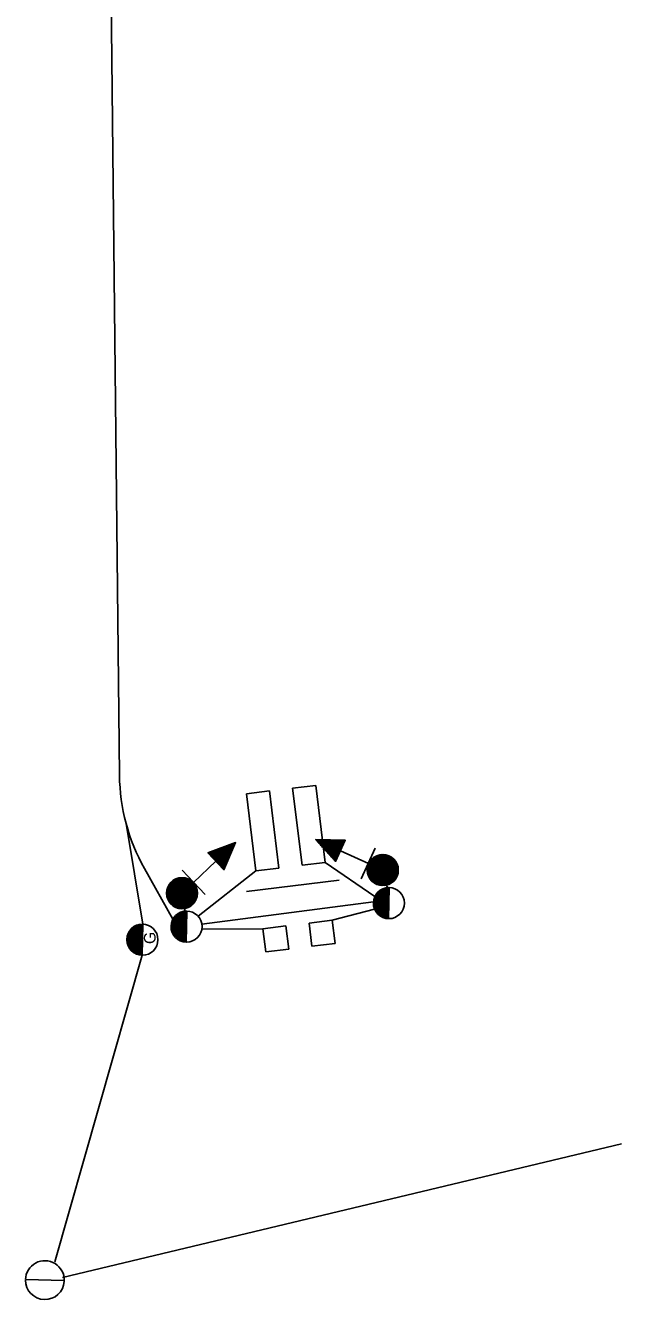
# Model space of a CAD drawing. Extents: x 584850 to 602551, y 145475 to 158627.
# Drawn here: x 585421.3 to 585574.8, y 151816.7 to 152144.7 of the extents above; entities that cross this region are included whole.
import ezdxf

# ---------------------------------------------------------------- set-up
doc = ezdxf.new("R2010")
doc.units = 0
doc.layers.add('Default', color=7, linetype='Continuous')
doc.layers.add('P_LTG', color=7, linetype='Continuous')

msp = doc.modelspace()

# ---------------------------------------------------------------- linework, layer by layer
at = {"layer": 'Default'}
for p, q in [((585442.26, 152251.68), (585445.51, 151951.65)), ((585490.11, 151948.32), (585496.07, 151949.05)), ((585490.11, 151948.32), (585492.53, 151928.47)), ((585496.07, 151949.05), (585498.49, 151929.2)), ((585478.2, 151946.87), (585484.15, 151947.6)), ((585478.2, 151946.87), (585480.62, 151927.02)), ((585484.15, 151947.6), (585486.58, 151927.74)), ((585451.49, 151913.31), (585447.21, 151939.25)), ((585468.86, 151931.91), (585468.83, 151931.11)), ((585469.11, 151932), (585469.07, 151930.85)), ((585469.11, 151932), (585474.36, 151931.84)), ((585469.36, 151932.09), (585469.32, 151930.59)), ((585469.61, 151932.18), (585469.56, 151930.33)), ((585469.74, 151932.23), (585474.46, 151932.09)), ((585469.87, 151932.28), (585469.8, 151930.08)), ((585470.12, 151932.37), (585470.05, 151929.82)), ((585470.37, 151932.46), (585470.29, 151929.56)), ((585470.37, 151932.46), (585474.57, 151932.34)), ((585470.63, 151932.55), (585470.53, 151929.31)), ((585470.88, 151932.65), (585470.77, 151929.05)), ((585471, 151932.69), (585474.68, 151932.59)), ((585471.13, 151932.74), (585471.02, 151928.79)), ((585471.38, 151932.83), (585471.26, 151928.53)), ((585471.64, 151932.92), (585471.5, 151928.28)), ((585471.64, 151932.92), (585474.79, 151932.83)), ((585471.89, 151933.02), (585471.74, 151928.02)), ((585472.14, 151933.11), (585471.99, 151927.76)), ((585472.39, 151933.2), (585472.23, 151927.51)), ((585472.27, 151933.16), (585474.89, 151933.08)), ((585472.65, 151933.29), (585472.48, 151927.52)), ((585472.9, 151933.39), (585472.75, 151928.14)), ((585472.9, 151933.39), (585475, 151933.33)), ((585473.15, 151933.48), (585473.02, 151928.76)), ((585473.41, 151933.57), (585473.28, 151929.37)), ((585473.53, 151933.62), (585475.11, 151933.57)), ((585473.66, 151933.67), (585473.55, 151929.99)), ((585473.91, 151933.76), (585473.82, 151930.61)), ((585474.16, 151933.85), (585474.09, 151931.23)), ((585474.16, 151933.85), (585475.21, 151933.82)), ((585474.42, 151933.94), (585474.36, 151931.84)), ((585474.67, 151934.04), (585474.62, 151932.46)), ((585474.8, 151934.08), (585475.32, 151934.07)), ((585474.92, 151934.13), (585474.89, 151933.08)), ((585475.18, 151934.22), (585475.16, 151933.7)), ((585475.43, 151934.31), (585475.43, 151934.31)), ((585496.02, 151935.07), (585496.02, 151935.07)), ((585496.2, 151934.87), (585496.69, 151935.06)), ((585496.47, 151934.58), (585496.29, 151935.07)), ((585496.38, 151934.68), (585497.37, 151935.05)), ((585496.93, 151934.08), (585496.56, 151935.06)), ((585496.57, 151934.48), (585498.04, 151935.03)), ((585496.75, 151934.28), (585498.71, 151935.02)), ((585497.38, 151933.58), (585496.83, 151935.06)), ((585496.93, 151934.08), (585499.39, 151935)), ((585497.84, 151933.09), (585497.1, 151935.05)), ((585497.11, 151933.88), (585500.06, 151934.99)), ((585497.29, 151933.68), (585500.73, 151934.98)), ((585498.29, 151932.59), (585497.37, 151935.05)), ((585497.47, 151933.48), (585501.4, 151934.96)), ((585498.74, 151932.09), (585497.64, 151935.04)), ((585497.66, 151933.28), (585502.08, 151934.95)), ((585497.84, 151933.09), (585502.75, 151934.93)), ((585499.2, 151931.59), (585497.91, 151935.03)), ((585498.02, 151932.89), (585503.42, 151934.92)), ((585499.65, 151931.1), (585498.17, 151935.03)), ((585498.2, 151932.69), (585503.53, 151934.69)), ((585498.38, 151932.49), (585503.39, 151934.37)), ((585500.11, 151930.6), (585498.44, 151935.02)), ((585498.56, 151932.29), (585503.24, 151934.05)), ((585500.56, 151930.1), (585498.71, 151935.02)), ((585498.74, 151932.09), (585503.1, 151933.73)), ((585498.93, 151931.89), (585502.95, 151933.41)), ((585501.01, 151929.61), (585498.98, 151935.01)), ((585499.11, 151931.69), (585502.8, 151933.08)), ((585501.26, 151929.67), (585499.25, 151935.01)), ((585499.29, 151931.5), (585502.66, 151932.76)), ((585499.47, 151931.3), (585502.51, 151932.44)), ((585501.4, 151929.99), (585499.52, 151935)), ((585499.65, 151931.1), (585502.37, 151932.12)), ((585501.55, 151930.32), (585499.79, 151935)), ((585501.7, 151930.64), (585500.06, 151934.99)), ((585501.84, 151930.96), (585500.33, 151934.98)), ((585501.99, 151931.28), (585500.6, 151934.98)), ((585502.13, 151931.6), (585500.87, 151934.97)), ((585502.28, 151931.93), (585501.14, 151934.97)), ((585502.43, 151932.25), (585501.4, 151934.96)), ((585502.57, 151932.57), (585501.67, 151934.96)), ((585502.72, 151932.89), (585501.94, 151934.95)), ((585502.86, 151933.21), (585502.21, 151934.94)), ((585509.65, 151928.89), (585502.4, 151932.18)), ((585503.01, 151933.54), (585502.48, 151934.94)), ((585503.16, 151933.86), (585502.75, 151934.93)), ((585503.3, 151934.18), (585503.02, 151934.93)), ((585503.45, 151934.5), (585503.29, 151934.92)), ((585503.59, 151934.82), (585503.56, 151934.92)), ((585509.56, 151928.93), (585511.33, 151932.84)), ((585464.54, 151924.05), (585470.34, 151929.51)), ((585468.35, 151931.72), (585468.35, 151931.62)), ((585468.44, 151931.52), (585474.14, 151931.35)), ((585468.48, 151931.77), (585474.25, 151931.6)), ((585468.6, 151931.81), (585468.59, 151931.36)), ((585468.69, 151931.26), (585474.03, 151931.1)), ((585468.93, 151931), (585473.93, 151930.86)), ((585469.17, 151930.75), (585473.82, 151930.61)), ((585469.41, 151930.49), (585473.71, 151930.36)), ((585469.66, 151930.23), (585473.61, 151930.12)), ((585469.9, 151929.97), (585473.5, 151929.87)), ((585470.14, 151929.72), (585473.39, 151929.62)), ((585470.39, 151929.46), (585473.28, 151929.37)), ((585470.63, 151929.2), (585473.18, 151929.13)), ((585470.87, 151928.94), (585473.07, 151928.88)), ((585471.11, 151928.69), (585472.96, 151928.63)), ((585492.53, 151928.47), (585498.49, 151929.2)), ((585498.49, 151929.2), (585511.28, 151920.42)), ((585499.83, 151930.9), (585502.22, 151931.8)), ((585500.02, 151930.7), (585502.07, 151931.47)), ((585500.2, 151930.5), (585501.93, 151931.15)), ((585500.38, 151930.3), (585501.78, 151930.83)), ((585500.56, 151930.1), (585501.64, 151930.51)), ((585500.74, 151929.9), (585501.49, 151930.19)), ((585500.92, 151929.71), (585501.34, 151929.86)), ((585501.11, 151929.51), (585501.2, 151929.54)), ((585509.56, 151928.93), (585507.79, 151925.02)), ((585509.34, 151927.27), (585516.3, 151929.88)), ((585509.34, 151927.01), (585516.47, 151929.69)), ((585509.35, 151927.53), (585516.13, 151930.08)), ((585509.37, 151927.79), (585515.92, 151930.25)), ((585509.37, 151926.76), (585516.61, 151929.49)), ((585509.4, 151926.52), (585516.74, 151929.28)), ((585509.43, 151928.07), (585515.7, 151930.43)), ((585509.45, 151926.28), (585516.87, 151929.07)), ((585509.49, 151928.35), (585515.47, 151930.6)), ((585509.52, 151926.05), (585516.97, 151928.85)), ((585509.59, 151925.82), (585517.06, 151928.63)), ((585509.6, 151928.65), (585515.19, 151930.75)), ((585511.6, 151923.63), (585509.66, 151928.79)), ((585509.72, 151928.95), (585514.9, 151930.9)), ((585511.91, 151923.49), (585509.8, 151929.1)), ((585509.9, 151929.27), (585514.55, 151931.02)), ((585512.2, 151923.4), (585509.96, 151929.36)), ((585510.11, 151929.61), (585514.15, 151931.13)), ((585512.48, 151923.33), (585510.12, 151929.62)), ((585512.76, 151923.28), (585510.3, 151929.82)), ((585510.45, 151929.99), (585513.69, 151931.21)), ((585513.02, 151923.25), (585510.48, 151930.02)), ((585513.29, 151923.23), (585510.67, 151930.2)), ((585513.54, 151923.25), (585510.86, 151930.36)), ((585510.96, 151930.44), (585513.02, 151931.21)), ((585513.79, 151923.27), (585511.06, 151930.52)), ((585514.03, 151923.29), (585511.27, 151930.65)), ((585514.27, 151923.35), (585511.48, 151930.76)), ((585514.5, 151923.41), (585511.7, 151930.88)), ((585514.73, 151923.49), (585511.92, 151930.96)), ((585514.95, 151923.59), (585512.15, 151931.04)), ((585515.17, 151923.69), (585512.38, 151931.11)), ((585515.38, 151923.81), (585512.62, 151931.15)), ((585515.59, 151923.94), (585512.86, 151931.19)), ((585515.79, 151924.08), (585513.11, 151931.21)), ((585515.98, 151924.25), (585513.36, 151931.21)), ((585516.17, 151924.43), (585513.62, 151931.21)), ((585516.36, 151924.62), (585513.89, 151931.17)), ((585516.53, 151924.85), (585514.17, 151931.13)), ((585516.7, 151925.08), (585514.45, 151931.06)), ((585516.85, 151925.36), (585514.74, 151930.95)), ((585516.99, 151925.65), (585515.05, 151930.83)), ((585517.12, 151926), (585515.37, 151930.65)), ((585517.23, 151926.38), (585515.71, 151930.42)), ((585517.3, 151926.89), (585516.08, 151930.12)), ((585517.3, 151927.57), (585516.53, 151929.62)), ((585451.94, 151927.66), (585459.28, 151914.62)), ((585464.61, 151924.11), (585461.67, 151927.24)), ((585480.62, 151927.02), (585465.74, 151915.38)), ((585471.36, 151928.43), (585472.85, 151928.39)), ((585471.6, 151928.17), (585472.75, 151928.14)), ((585471.84, 151927.92), (585472.64, 151927.89)), ((585472.08, 151927.66), (585472.53, 151927.65)), ((585472.33, 151927.4), (585472.43, 151927.4)), ((585480.62, 151927.02), (585486.58, 151927.74)), ((585510.56, 151924.36), (585509.35, 151927.57)), ((585510.11, 151924.88), (585509.35, 151926.89)), ((585510.94, 151924.03), (585509.43, 151928.05)), ((585511.28, 151923.8), (585509.53, 151928.46)), ((585509.68, 151925.6), (585517.15, 151928.41)), ((585509.79, 151925.39), (585517.2, 151928.17)), ((585509.9, 151925.17), (585517.25, 151927.93)), ((585510.04, 151924.97), (585517.3, 151927.69)), ((585510.19, 151924.77), (585517.31, 151927.44)), ((585510.34, 151924.57), (585517.32, 151927.19)), ((585510.53, 151924.38), (585517.31, 151926.93)), ((585510.72, 151924.2), (585517.27, 151926.66)), ((585510.95, 151924.02), (585517.24, 151926.39)), ((585511.19, 151923.86), (585517.15, 151926.1)), ((585511.45, 151923.7), (585517.06, 151925.81)), ((585511.76, 151923.56), (585516.92, 151925.5)), ((585457.7, 151922.11), (585465.55, 151921.88)), ((585457.8, 151922.46), (585457.74, 151920.31)), ((585457.77, 151922.35), (585465.51, 151922.12)), ((585457.84, 151922.59), (585465.44, 151922.37)), ((585457.92, 151922.83), (585465.37, 151922.61)), ((585458.06, 151923.09), (585457.96, 151919.66)), ((585458.04, 151923.06), (585465.27, 151922.85)), ((585458.17, 151923.3), (585465.15, 151923.09)), ((585458.31, 151923.53), (585458.19, 151919.23)), ((585458.32, 151923.53), (585465.03, 151923.34)), ((585458.56, 151923.86), (585458.42, 151918.88)), ((585458.49, 151923.77), (585464.86, 151923.58)), ((585458.81, 151924.12), (585458.65, 151918.61)), ((585458.69, 151924), (585464.68, 151923.83)), ((585459.06, 151924.35), (585458.88, 151918.36)), ((585458.94, 151924.24), (585464.45, 151924.08)), ((585459.3, 151924.53), (585459.12, 151918.17)), ((585459.21, 151924.47), (585464.19, 151924.32)), ((585459.55, 151924.69), (585459.35, 151917.98)), ((585459.55, 151924.7), (585463.85, 151924.57)), ((585459.79, 151924.83), (585459.59, 151917.84)), ((585460.03, 151924.94), (585459.82, 151917.71)), ((585460, 151924.93), (585463.43, 151924.83)), ((585460.28, 151925.05), (585460.06, 151917.6)), ((585460.52, 151925.11), (585460.3, 151917.51)), ((585460.76, 151925.17), (585460.53, 151917.43)), ((585460.65, 151925.15), (585462.8, 151925.08)), ((585461, 151925.23), (585460.77, 151917.38)), ((585461.24, 151925.25), (585461.01, 151917.33)), ((585461.48, 151925.26), (585461.25, 151917.29)), ((585461.72, 151925.27), (585461.49, 151917.29)), ((585461.96, 151925.25), (585461.73, 151917.29)), ((585462.2, 151925.22), (585461.97, 151917.3)), ((585462.44, 151925.18), (585462.21, 151917.34)), ((585462.68, 151925.12), (585462.45, 151917.38)), ((585462.92, 151925.05), (585462.7, 151917.44)), ((585463.16, 151924.95), (585462.94, 151917.52)), ((585463.39, 151924.84), (585463.18, 151917.6)), ((585463.63, 151924.72), (585463.42, 151917.73)), ((585463.86, 151924.56), (585463.67, 151917.86)), ((585464.1, 151924.4), (585463.91, 151918.02)), ((585464.33, 151924.19), (585464.16, 151918.21)), ((585464.57, 151923.96), (585464.4, 151918.43)), ((585464.61, 151924.11), (585467.56, 151920.99)), ((585464.8, 151923.67), (585464.65, 151918.7)), ((585465.03, 151923.35), (585464.9, 151919.03)), ((585465.26, 151922.89), (585465.15, 151919.43)), ((585465.48, 151922.25), (585465.41, 151920.05)), ((585478.25, 151921.69), (585490.16, 151923.14)), ((585490.16, 151923.14), (585502.07, 151924.6)), ((585514.9, 151922.72), (585510.91, 151918.89)), ((585514.97, 151922.46), (585510.92, 151918.56)), ((585514.96, 151922.12), (585510.93, 151918.24)), ((585514.52, 151922.7), (585510.95, 151919.26)), ((585514.12, 151922.64), (585511.01, 151919.65)), ((585513.66, 151922.53), (585511.17, 151920.13)), ((585513.04, 151922.27), (585511.46, 151920.75)), ((585512.09, 151923.43), (585516.76, 151925.18)), ((585512.49, 151923.32), (585516.51, 151924.84)), ((585512.7, 151922.05), (585514.92, 151919.75)), ((585512.9, 151922.19), (585514.93, 151920.09)), ((585512.99, 151923.26), (585516.2, 151924.46)), ((585513.12, 151922.31), (585514.93, 151920.43)), ((585513.36, 151922.41), (585514.94, 151920.77)), ((585513.6, 151922.51), (585514.95, 151921.11)), ((585513.68, 151923.26), (585515.69, 151924.01)), ((585513.86, 151922.58), (585514.95, 151921.45)), ((585514.13, 151922.64), (585514.96, 151921.79)), ((585514.51, 151922.71), (585514.29, 151923.35)), ((585514.42, 151922.69), (585514.96, 151922.12)), ((585514.73, 151922.71), (585514.97, 151922.46)), ((585514.83, 151914.73), (585514.98, 151922.73)), ((585514.93, 151922.73), (585514.97, 151922.69)), ((585457.62, 151921.39), (585465.59, 151921.16)), ((585457.62, 151921.15), (585465.58, 151920.92)), ((585457.63, 151921.63), (585465.6, 151921.4)), ((585457.63, 151920.91), (585465.56, 151920.68)), ((585457.66, 151920.67), (585465.5, 151920.44)), ((585457.67, 151921.87), (585465.58, 151921.64)), ((585457.71, 151920.43), (585465.45, 151920.2)), ((585457.76, 151920.19), (585465.38, 151919.97)), ((585457.85, 151919.95), (585465.28, 151919.73)), ((585457.94, 151919.7), (585465.18, 151919.49)), ((585458.05, 151919.46), (585465.04, 151919.26)), ((585458.2, 151919.22), (585464.9, 151919.02)), ((585458.34, 151918.97), (585464.73, 151918.79)), ((585458.54, 151918.73), (585464.52, 151918.55)), ((585466.74, 151913.32), (585510.91, 151919.04)), ((585510.92, 151919.06), (585514.83, 151915)), ((585510.96, 151919.36), (585514.84, 151915.34)), ((585514.96, 151921.79), (585510.99, 151917.96)), ((585511.01, 151919.66), (585514.84, 151915.68)), ((585514.95, 151921.45), (585511.04, 151917.68)), ((585511.09, 151919.92), (585514.85, 151916.02)), ((585514.95, 151921.11), (585511.13, 151917.43)), ((585511.18, 151920.17), (585514.86, 151916.36)), ((585514.94, 151920.77), (585511.22, 151917.19)), ((585511.28, 151920.41), (585514.86, 151916.69)), ((585514.93, 151920.43), (585511.32, 151916.95)), ((585511.4, 151920.64), (585514.87, 151917.03)), ((585514.93, 151920.09), (585511.45, 151916.74)), ((585511.52, 151920.86), (585514.88, 151917.37)), ((585514.92, 151919.75), (585511.57, 151916.53)), ((585511.66, 151921.06), (585514.88, 151917.71)), ((585514.91, 151919.41), (585511.71, 151916.33)), ((585511.81, 151921.25), (585514.89, 151918.05)), ((585514.91, 151919.07), (585511.87, 151916.14)), ((585511.96, 151921.44), (585514.89, 151918.39)), ((585514.9, 151918.73), (585512.02, 151915.96)), ((585512.13, 151921.6), (585514.9, 151918.73)), ((585512.31, 151921.77), (585514.91, 151919.07)), ((585512.49, 151921.92), (585514.91, 151919.41)), ((585458.76, 151918.48), (585464.29, 151918.32)), ((585462.78, 151916.68), (585458.8, 151912.85)), ((585462.86, 151916.42), (585458.8, 151912.52)), ((585462.85, 151916.08), (585458.82, 151912.2)), ((585462.41, 151916.66), (585458.83, 151913.22)), ((585462.84, 151915.75), (585458.87, 151911.92)), ((585462, 151916.6), (585458.89, 151913.61)), ((585459.04, 151918.23), (585464, 151918.09)), ((585461.54, 151916.49), (585459.05, 151914.09)), ((585459.34, 151917.98), (585463.66, 151917.86)), ((585460.92, 151916.23), (585459.34, 151914.71)), ((585459.78, 151917.73), (585463.24, 151917.63)), ((585460.02, 151915.56), (585462.79, 151912.69)), ((585460.2, 151915.73), (585462.79, 151913.03)), ((585460.38, 151915.88), (585462.8, 151913.37)), ((585460.41, 151917.47), (585462.61, 151917.41)), ((585460.58, 151916.01), (585462.8, 151913.71)), ((585460.79, 151916.15), (585462.81, 151914.05)), ((585461.01, 151916.27), (585462.82, 151914.39)), ((585461.24, 151916.37), (585462.82, 151914.73)), ((585461.48, 151916.47), (585462.83, 151915.07)), ((585461.74, 151916.54), (585462.84, 151915.41)), ((585462.02, 151916.6), (585462.84, 151915.75)), ((585462.41, 151916.67), (585462.24, 151917.33)), ((585462.3, 151916.65), (585462.85, 151916.08)), ((585462.61, 151916.67), (585462.86, 151916.42)), ((585462.71, 151908.69), (585462.86, 151916.69)), ((585462.82, 151916.69), (585462.86, 151916.65)), ((585500.31, 151914.31), (585511.21, 151917.19)), ((585510.91, 151918.72), (585514.75, 151914.74)), ((585510.92, 151918.36), (585514.38, 151914.77)), ((585510.99, 151917.94), (585513.97, 151914.85)), ((585511.12, 151917.47), (585513.49, 151915)), ((585511.39, 151916.84), (585512.88, 151915.3)), ((585514.89, 151918.39), (585512.2, 151915.8)), ((585514.89, 151918.05), (585512.38, 151915.64)), ((585514.88, 151917.71), (585512.57, 151915.48)), ((585514.88, 151917.37), (585512.78, 151915.35)), ((585514.87, 151917.03), (585512.99, 151915.23)), ((585514.86, 151916.69), (585513.21, 151915.11)), ((585514.86, 151916.36), (585513.46, 151915.01)), ((585514.85, 151916.02), (585513.71, 151914.92)), ((585514.84, 151915.68), (585513.98, 151914.85)), ((585451.41, 151913.3), (585447.43, 151909.47)), ((585451.49, 151913.04), (585447.43, 151909.14)), ((585451.48, 151912.7), (585447.45, 151908.82)), ((585451.04, 151913.28), (585447.47, 151909.84)), ((585451.47, 151912.36), (585447.51, 151908.54)), ((585450.63, 151913.22), (585447.52, 151910.22)), ((585450.17, 151913.11), (585447.68, 151910.71)), ((585449.55, 151912.85), (585447.97, 151911.33)), ((585448.65, 151912.18), (585451.42, 151909.31)), ((585448.83, 151912.34), (585451.42, 151909.65)), ((585449.01, 151912.5), (585451.43, 151909.99)), ((585449.22, 151912.63), (585451.44, 151910.33)), ((585449.42, 151912.77), (585451.44, 151910.67)), ((585449.64, 151912.88), (585451.45, 151911.01)), ((585449.88, 151912.99), (585451.46, 151911.35)), ((585450.11, 151913.09), (585451.46, 151911.69)), ((585450.38, 151913.16), (585451.47, 151912.03)), ((585450.65, 151913.22), (585451.47, 151912.36)), ((585450.93, 151913.27), (585451.48, 151912.7)), ((585451.25, 151913.29), (585451.49, 151913.04)), ((585451.34, 151905.31), (585451.49, 151913.31)), ((585451.45, 151913.31), (585451.49, 151913.26)), ((585458.8, 151912.68), (585462.63, 151908.7)), ((585458.81, 151913.02), (585462.72, 151908.96)), ((585458.81, 151912.32), (585462.27, 151908.73)), ((585458.85, 151913.32), (585462.72, 151909.3)), ((585458.89, 151913.62), (585462.73, 151909.64)), ((585462.84, 151915.41), (585458.93, 151911.64)), ((585458.98, 151913.88), (585462.73, 151909.98)), ((585462.83, 151915.07), (585459.02, 151911.39)), ((585459.06, 151914.13), (585462.74, 151910.32)), ((585462.82, 151914.73), (585459.11, 151911.15)), ((585459.17, 151914.37), (585462.75, 151910.65)), ((585462.82, 151914.39), (585459.21, 151910.91)), ((585459.28, 151914.6), (585462.75, 151910.99)), ((585462.81, 151914.05), (585459.33, 151910.7)), ((585459.4, 151914.82), (585462.76, 151911.33)), ((585462.8, 151913.71), (585459.46, 151910.49)), ((585459.55, 151915.02), (585462.77, 151911.67)), ((585462.8, 151913.37), (585459.6, 151910.29)), ((585459.69, 151915.21), (585462.77, 151912.01)), ((585462.79, 151913.03), (585459.75, 151910.1)), ((585459.84, 151915.4), (585462.78, 151912.35)), ((585462.79, 151912.69), (585459.91, 151909.92)), ((585462.78, 151912.35), (585460.08, 151909.76)), ((585482.44, 151912.13), (585488.39, 151912.85)), ((585489.12, 151906.9), (585488.39, 151912.85)), ((585494.35, 151913.58), (585500.31, 151914.31)), ((585494.35, 151913.58), (585495.08, 151907.63)), ((585501.03, 151908.35), (585500.31, 151914.31)), ((585514.84, 151915.34), (585514.27, 151914.79)), ((585514.83, 151915), (585514.57, 151914.75)), ((585514.83, 151914.73), (585514.83, 151914.73)), ((585514.83, 151914.73), (585514.83, 151914.73)), ((585447.43, 151909.3), (585451.27, 151905.32)), ((585447.44, 151909.64), (585451.35, 151905.58)), ((585447.44, 151908.94), (585450.9, 151905.35)), ((585447.48, 151909.94), (585451.35, 151905.92)), ((585447.53, 151910.24), (585451.36, 151906.26)), ((585451.47, 151912.03), (585447.56, 151908.26)), ((585447.61, 151910.49), (585451.37, 151906.6)), ((585451.46, 151911.69), (585447.65, 151908.01)), ((585447.7, 151910.75), (585451.37, 151906.93)), ((585451.46, 151911.35), (585447.74, 151907.77)), ((585447.8, 151910.99), (585451.38, 151907.27)), ((585451.45, 151911.01), (585447.84, 151907.53)), ((585447.92, 151911.22), (585451.39, 151907.61)), ((585451.44, 151910.67), (585447.97, 151907.32)), ((585448.03, 151911.44), (585451.39, 151907.95)), ((585451.44, 151910.33), (585448.09, 151907.11)), ((585448.18, 151911.64), (585451.4, 151908.29)), ((585451.43, 151909.99), (585448.23, 151906.91)), ((585448.33, 151911.83), (585451.4, 151908.63)), ((585451.42, 151909.65), (585448.39, 151906.72)), ((585448.48, 151912.02), (585451.41, 151908.97)), ((585451.42, 151909.31), (585448.54, 151906.54)), ((585451.41, 151908.97), (585448.72, 151906.37)), ((585455.33, 151910.29), (585455.22, 151910.25)), ((585458.88, 151911.9), (585461.86, 151908.81)), ((585459, 151911.43), (585461.38, 151908.96)), ((585459.27, 151910.8), (585460.76, 151909.26)), ((585462.77, 151912.01), (585460.27, 151909.6)), ((585462.77, 151911.67), (585460.45, 151909.44)), ((585462.76, 151911.33), (585460.66, 151909.31)), ((585462.75, 151910.99), (585460.88, 151909.19)), ((585462.75, 151910.65), (585461.1, 151909.07)), ((585462.74, 151910.32), (585461.35, 151908.97)), ((585462.73, 151909.98), (585461.6, 151908.88)), ((585462.73, 151909.64), (585461.87, 151908.81)), ((585462.72, 151909.3), (585462.16, 151908.75)), ((585462.72, 151908.96), (585462.46, 151908.71)), ((585482.44, 151912.13), (585466.72, 151911.98)), ((585482.44, 151912.13), (585483.17, 151906.17)), ((585447.51, 151908.52), (585450.49, 151905.43)), ((585447.63, 151908.05), (585450.01, 151905.58)), ((585447.9, 151907.42), (585449.39, 151905.88)), ((585451.4, 151908.63), (585448.9, 151906.22)), ((585451.4, 151908.29), (585449.08, 151906.06)), ((585451.39, 151907.95), (585449.3, 151905.93)), ((585451.39, 151907.61), (585449.51, 151905.81)), ((585451.38, 151907.27), (585449.73, 151905.69)), ((585451.37, 151906.93), (585449.98, 151905.59)), ((585451.37, 151906.6), (585450.23, 151905.5)), ((585451.36, 151906.26), (585450.5, 151905.43)), ((585451.35, 151905.92), (585450.79, 151905.37)), ((585462.71, 151908.69), (585462.71, 151908.69)), ((585462.71, 151908.69), (585462.71, 151908.69)), ((585483.17, 151906.17), (585489.12, 151906.9)), ((585495.08, 151907.63), (585501.03, 151908.35)), ((585451.34, 151905.31), (585428.85, 151826.34)), ((585451.35, 151905.58), (585451.09, 151905.33)), ((585451.34, 151905.31), (585451.34, 151905.31)), ((585451.34, 151905.31), (585451.34, 151905.31)), ((585430.86, 151822.33), (585574.82, 151856.77))]:
    msp.add_line(p, q, dxfattribs=at)
for points in [[(585468.28, 151931.69), (585475.43, 151934.31), (585472.39, 151927.33)], [(585501.16, 151929.45), (585496.02, 151935.07), (585503.64, 151934.92)]]:
    msp.add_lwpolyline(points, close=True, dxfattribs=at)
for centre in [(585513.33, 151927.23), (585461.61, 151921.28), (585514.9, 151918.73), (585462.79, 151912.69), (585451.42, 151909.31)]:
    msp.add_circle(centre, 4, dxfattribs=at)
for centre, radius, start, end in [((585495.51, 151952.19), 50, 180.6202, 209.3773), ((585514.9, 151918.73), 4, 88.9257, 268.9257), ((585462.79, 151912.69), 4, 88.9257, 268.9257), ((585451.42, 151909.31), 4, 88.9257, 268.9257)]:
    msp.add_arc(centre, radius, start, end, dxfattribs=at)
at = {"layer": 'P_LTG'}
for p, q in [((585431.3, 151821.53), (585421.3, 151821.79)), ((585431.29, 151821.34), (585431.29, 151821.53))]:
    msp.add_line(p, q, dxfattribs=at)
for start, end in [(358.556, 178.556), (178.556, 178.6415), (179.9464, 356.3235), (358.0488, 358.556)]:
    msp.add_arc((585426.3, 151821.66), 5, start, end, dxfattribs=at)

# ---------------------------------------------------------------- texts
at = {"layer": 'Default'}
msp.add_text('G', height=3, rotation=89.3623, dxfattribs=at).set_placement((585454.79, 151908.18))

doc.saveas('drawing.dxf')
